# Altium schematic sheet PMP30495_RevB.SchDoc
size 431 x 279 mm; Date: Not shown in title block; ApprovedBy: Not shown in title block; CheckedBy: Not shown in title block; Author: Not shown in title block; CompanyName: Not shown in title block; Engineer: Not shown in title block; Organization: Not shown in title block; Address1: Not shown in title block; Address2: Not shown in title block; Address3: Not shown in title block; Address4: Not shown in title block; DocumentNumber: 1; Revision: Use project parameter SCH_Rev; SheetNumber: 2; SheetTotal: 3; PageSetup: Record=PageOptions¦CenterHorizontal=True¦CenterVertical=True¦PrintScale=1.00¦XCorrection=1.00¦YCorrection=1.00¦PrintKind=0¦BorderSize=5000000¦LeftOffset=0¦BottomOffset=0¦Orientation=2¦PaperLength=1000¦PaperWidth=1000¦Scale=100¦PaperSource=15¦PrintQuality=600¦MediaType=1¦DitherType=10¦PaperKind=Letter¦PrintScaleMode=1
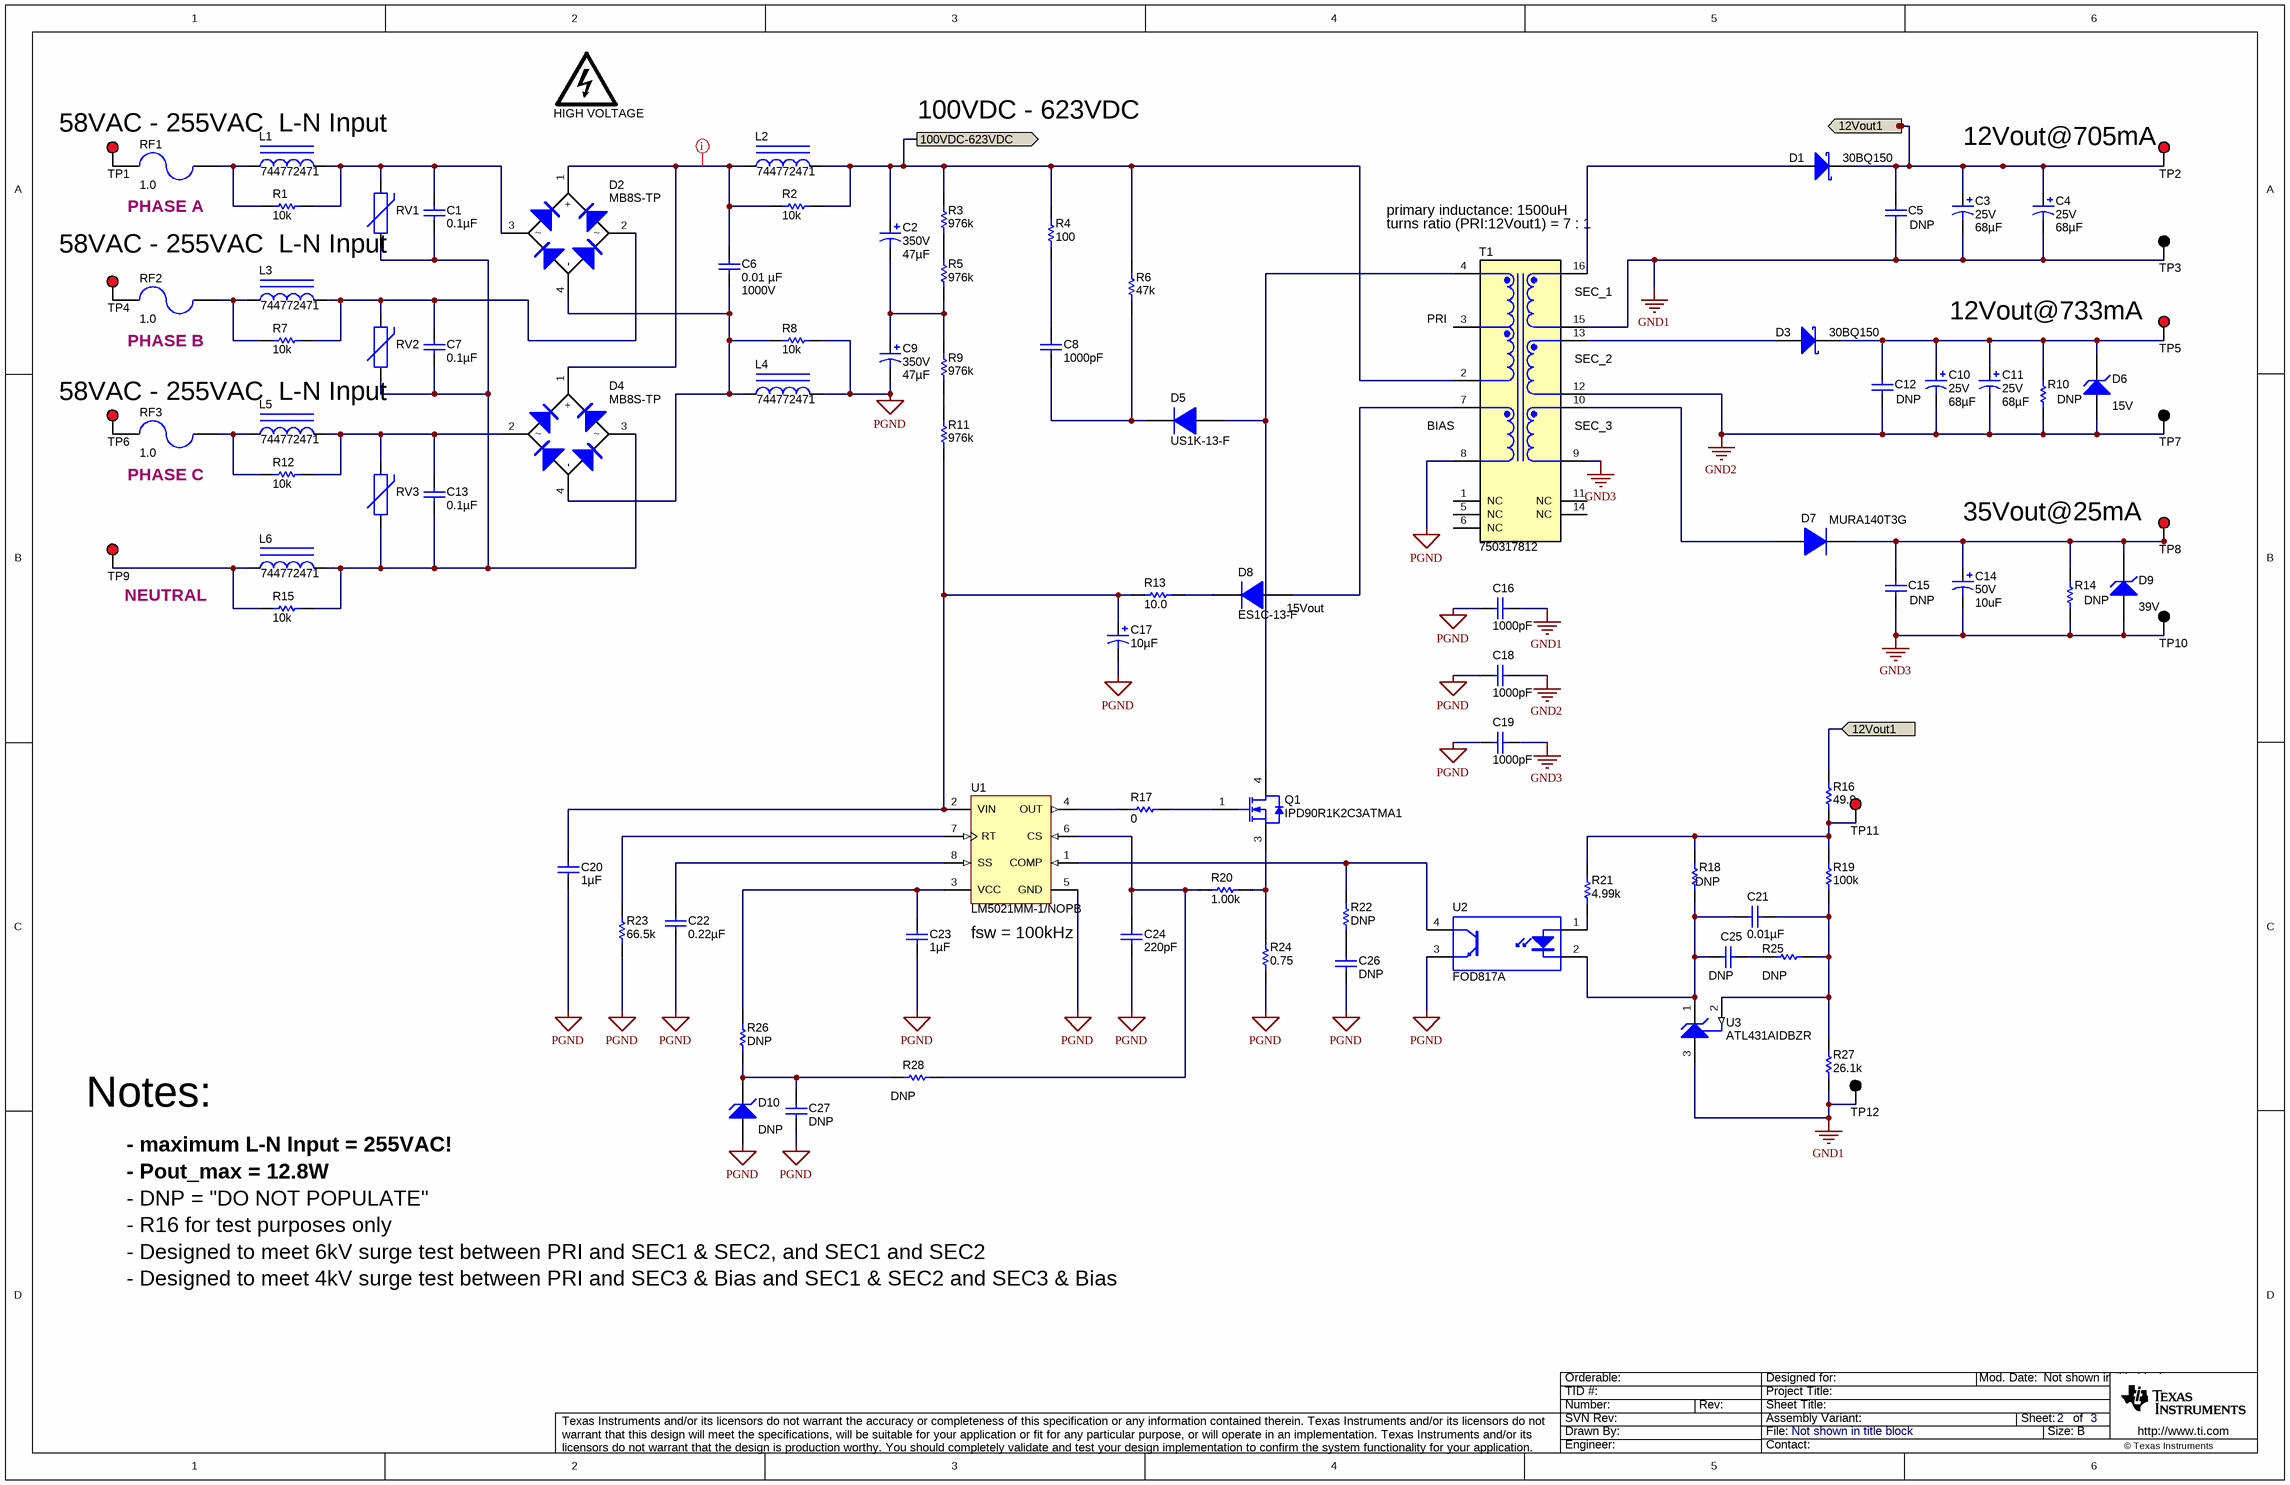
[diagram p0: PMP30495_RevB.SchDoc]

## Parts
C1  ValueDisplayed: 0.1µF  [B32921_1300x1200x600]  (hidden comment: B32921C3104M)
C2  VDC_V: 350V  ValueDisplayed: 47µF  [VR_1600x2500]  (hidden comment: UVK2V470MHD)
C3  VDC_V: 25V  ValueDisplayed: 68µF  [Nichicon_800x1000]  (hidden comment: UWG1E680MNL1GS)
C4  VDC_V: 25V  ValueDisplayed: 68µF  [Nichicon_800x1000]  (hidden comment: UWG1E680MNL1GS)
C5  value DNP  [1206]  (hidden comment: Used in BOM report)
C6  ValueDisplayed: 0.01 µF  Value2: 1000V  [B32652A_500x1050x1800]  (hidden comment: B32652A0103K)
C7  ValueDisplayed: 0.1µF  [B32921_1300x1200x600]  (hidden comment: B32921C3104M)
C8  ValueDisplayed: 1000pF  [1206]  (hidden comment: GRM31BR73A102KW01L)
C9  VDC_V: 350V  ValueDisplayed: 47µF  [VR_1600x2500]  (hidden comment: UVK2V470MHD)
C10  VDC_V: 25V  ValueDisplayed: 68µF  [Nichicon_800x1000]  (hidden comment: UWG1E680MNL1GS)
C11  VDC_V: 25V  ValueDisplayed: 68µF  [Nichicon_800x1000]  (hidden comment: UWG1E680MNL1GS)
C12  value DNP  [1206]  (hidden comment: Used in BOM report)
C13  ValueDisplayed: 0.1µF  [B32921_1300x1200x600]  (hidden comment: B32921C3104M)
C14  VDC_V: 50V  ValueDisplayed: 10uF  [SM_RADIAL_6.3AMM]  (hidden comment: UUD1H100MCL1GS)
C15  value DNP  [1206]  (hidden comment: Used in BOM report)
C16  ValueDisplayed: 1000pF  [CAPRD750W60D750H1050]  (hidden comment: VY2102M29Y5UG63V7)
C17  ValueDisplayed: 10µF  [PW_500x700]  (hidden comment: UPW1V100MDD6)
C18  ValueDisplayed: 1000pF  [CAPRD750W60D750H1050]  (hidden comment: VY2102M29Y5UG63V7)
C19  ValueDisplayed: 1000pF  [CAPRD750W60D750H1050]  (hidden comment: VY2102M29Y5UG63V7)
C20  ValueDisplayed: 1µF  [0805_HV]  (hidden comment: 08055C105KAT2A)
C21  ValueDisplayed: 0.01µF  [0603]  (hidden comment: C0603C103J5RACTU)
C22  ValueDisplayed: 0.22µF  [0603]  (hidden comment: C0603C224J3RAC7867)
C23  ValueDisplayed: 1µF  [0805_HV]  (hidden comment: 08055C105KAT2A)
C24  ValueDisplayed: 220pF  [0603]  (hidden comment: C0603C221K5RACTU)
C25  value DNP  [0603_HV]  (hidden comment: Used in BOM report)
C26  value DNP  [0603_HV]  (hidden comment: Used in BOM report)
C27  value DNP  [0805]  (hidden comment: Used in BOM report)
D1  30BQ150  [SMC]
D2  MB8S-TP  [MBS-1]
D3  30BQ150  [SMC]
D4  MB8S-TP  [MBS-1]
D5  US1K-13-F  [SMA]
D6  value 15V  [SOD-123]  (hidden comment: MMSZ5245B-7-F)
D7  MURA140T3G  [SMA]
D8  ES1C-13-F  [SMA]
D9  value 39V  [SMA]  (hidden comment: 3SMAJ5939B-TP)
D10  value DNP  [SOD-123]  (hidden comment: Used in BOM report)
HIGH_VOLTAGE  DANGER HIGH VOLTAGE  [IEC_HighVoltage_Small]  (value not drawn)  (no BOM)
L1  744772471  [WE_TI_8095_Unshielded]
L2  744772471  [WE_TI_8095_Unshielded]
L3  744772471  [WE_TI_8095_Unshielded]
L4  744772471  [WE_TI_8095_Unshielded]
L5  744772471  [WE_TI_8095_Unshielded]
L6  744772471  [WE_TI_8095_Unshielded]
Q1  IPD90R1K2C3ATMA1  [DPAK]
R1  value 10k  [1206L]  (hidden comment: CRCW120610K0JNEA)
R2  value 10k  [1206L]  (hidden comment: CRCW120610K0JNEA)
R3  ValueDisplayed: 976k  [1206]  (hidden comment: CRCW1206976KFKEA)
R4  ValueDisplayed: 100  [2010]  (hidden comment: CRCW2010100RFKEF)
R5  ValueDisplayed: 976k  [1206]  (hidden comment: CRCW1206976KFKEA)
R6  ValueDisplayed: 47k  [2512]  (hidden comment: CRCW251247K0JNEG)
R7  value 10k  [1206L]  (hidden comment: CRCW120610K0JNEA)
R8  value 10k  [1206L]  (hidden comment: CRCW120610K0JNEA)
R9  ValueDisplayed: 976k  [1206]  (hidden comment: CRCW1206976KFKEA)
R10  value DNP  [0805]  (hidden comment: Used in BOM report)
R11  ValueDisplayed: 976k  [1206]  (hidden comment: CRCW1206976KFKEA)
R12  value 10k  [1206L]  (hidden comment: CRCW120610K0JNEA)
R13  ValueDisplayed: 10.0  [0805_HV]  (hidden comment: CRCW080510R0FKEA)
R14  value DNP  [0805]  (hidden comment: Used in BOM report)
R15  value 10k  [1206L]  (hidden comment: CRCW120610K0JNEA)
R16  ValueDisplayed: 49.9  [0603]  (hidden comment: CRCW060349R9FKEA)
R17  ValueDisplayed: 0  [0805_HV]  (hidden comment: CRCW08050000Z0EA)
R18  value DNP  [0603]  (hidden comment: Used in BOM report)
R19  ValueDisplayed: 100k  [0603]  (hidden comment: CRCW0603100KFKEA)
R20  ValueDisplayed: 1.00k  [0603]  (hidden comment: CRCW06031K00FKEA)
R21  ValueDisplayed: 4.99k  [0603]  (hidden comment: CRCW06034K99FKEA)
R22  value DNP  [0603_HV]  (hidden comment: Used in BOM report)
R23  ValueDisplayed: 66.5k  [0603]  (hidden comment: CRCW060366K5FKEA)
R24  ValueDisplayed: 0.75  [1206]  (hidden comment: ERJ-8RQFR75)
R25  value DNP  [0603_HV]  (hidden comment: Used in BOM report)
R26  value DNP  [0603]  (hidden comment: Used in BOM report)
R27  ValueDisplayed: 26.1k  [0603]  (hidden comment: CRCW060326K1FKEA)
R28  value DNP  [0603]  (hidden comment: Used in BOM report)
RF1  ValueDisplayed: 1.0  [SPP_1020x380]  (hidden comment: SPP1UL1R00JLF)
RF2  ValueDisplayed: 1.0  [SPP_1020x380]  (hidden comment: SPP1UL1R00JLF)
RF3  ValueDisplayed: 1.0  [SPP_1020x380]  (hidden comment: SPP1UL1R00JLF)
RV1  B72210S2301K101  [EPCOS_B72210S2301K101]  (value not drawn)
RV2  B72210S2301K101  [EPCOS_B72210S2301K101]  (value not drawn)
RV3  B72210S2301K101  [EPCOS_B72210S2301K101]  (value not drawn)
T1  750317812  [Wurth_750317812]
TP1  5000  [Keystone5000]  (value not drawn)
TP2  5000  [Keystone5000]  (value not drawn)
TP3  5001  [Keystone5001]  (value not drawn)
TP4  5000  [Keystone5000]  (value not drawn)
TP5  5000  [Keystone5000]  (value not drawn)
TP6  5000  [Keystone5000]  (value not drawn)
TP7  5001  [Keystone5001]  (value not drawn)
TP8  5000  [Keystone5000]  (value not drawn)
TP9  5000  [Keystone5000]  (value not drawn)
TP10  5001  [Keystone5001]  (value not drawn)
TP11  5000  [Keystone5000]  (value not drawn)
TP12  5001  [Keystone5001]  (value not drawn)
U1  LM5021MM-1/NOPB  [MUA08A_N]
U2  FOD817A  [DIP-4]
U3  ATL431AIDBZR  [DBZ0003A_N]

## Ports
12Vout1 (in), 100VDC-623VDC (out)

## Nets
GND1: C3.2(-) C4.2(-) C5.2 C16.1 R27.1 T1.15 TP3.1 TP12.1 U3.3(ANODE)
GND2: C10.2(-) C11.2(-) C12.2 C18.1 D6.2(A) R10.1 T1.12 TP7.1
GND3: C14.2(-) C15.2 C19.1 D9.2(A) R14.1 T1.9 TP10.1
PGND: C9.2(-) C16.2 C17.2(-) C18.2 C19.2 C20.2 C22.2 C23.2 C24.2 C26.2 C27.2 D10.2(A) L4.2 R8.2 R23.1 R24.1 T1.8 U1.5(GND) U2.3(E)
12Vout1: C3.1(+) C4.1(+) C5.1 D1.1(K) R16.2 TP2.1 ; port 12Vout1
100VDC-623VDC: C2.1(+) L2.2 R2.2 R3.2 R4.2 R6.2 T1.2 ; port 100VDC-623VDC
NetC1_1: C1.1 D2.3 L1.2 R1.2 RV1.2
NetC1_2: C1.2 C7.2 C13.2 D4.3 L6.2 R15.2 RV1.1 RV2.1 RV3.1
NetC2_2: C2.2(-) C9.1(+) R5.1 R9.2
NetC6_1: C6.1 D2.1(+) D4.1(+) L2.1 R2.1
NetC6_2: C6.2 D2.4(-) D4.4(-) L4.1 R8.1
NetC7_1: C7.1 D2.2 L3.2 R7.2 RV2.2
NetC8_1: C8.1 R4.1
NetC8_2: C8.2 D5.1(K) R6.1
NetC10_1: C10.1(+) C11.1(+) C12.1 D3.1(K) D6.1(K) R10.2 TP5.1
NetC13_1: C13.1 D4.2 L5.2 R12.2 RV3.2
NetC14_1: C14.1(+) C15.1 D7.1(K) D9.1(K) R14.2 TP8.1
NetC17_1: C17.1(+) C20.1 R11.1 R13.1 U1.2(VIN)
NetC21_1: C21.1 R19.1 R25.1 R27.2 U3.2(REF)
NetC21_2: C21.2 C25.1 R18.1 U2.2(K) U3.1(CATHODE)
NetC22_1: C22.1 U1.8(SS)
NetC23_1: C23.1 R26.2 U1.3(VCC)
NetC24_1: C24.1 R20.1 R28.2 U1.6(CS)
NetC25_2: C25.2 R25.2
NetC26_1: C26.1 R22.1
NetC27_1: C27.1 D10.1(K) R26.1 R28.1
NetD1_2: D1.2(A) T1.16
NetD3_2: D3.2(A) T1.13
NetD5_2: D5.2(A) Q1.4(D) T1.4
NetD7_2: D7.2(A) T1.10
NetD8_1: D8.1(K) R13.2
NetD8_2: D8.2(A) T1.7
NetL1_1: L1.1 R1.1 RF1.1
NetL3_1: L3.1 R7.1 RF2.1
NetL5_1: L5.1 R12.1 RF3.1
NetL6_1: L6.1 R15.1 TP9.1
NetQ1_1: Q1.1(G) R17.2
NetQ1_3: Q1.3(S) R20.2 R24.2
NetR3_1: R3.1 R5.2
NetR9_1: R9.1 R11.2
NetR16_1: R16.1 R18.2 R19.2 R21.2 TP11.1
NetR17_1: R17.1 U1.4(OUT)
NetR21_1: R21.1 U2.1(A)
NetR22_2: R22.2 U1.1(COMP) U2.4(C)
NetR23_2: R23.2 U1.7(RT)
NetRF1_2: RF1.2 TP1.1
NetRF2_2: RF2.2 TP4.1
NetRF3_2: RF3.2 TP6.1

Not connected (* = marked no-connect by the designer): T1 1(NC) 3 5(NC) 6(NC) 11(NC) 14(NC)

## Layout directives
rule Clearance Constraint [Clearance = 25mil]: NetC6_1

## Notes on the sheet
- (near TP1) 58VAC - 255VAC  L-N Input
- 100VDC - 623VDC
- 12Vout@705mA
- (near RF1) PHASE A
- primary inductance: 1500uH
- (near T1) turns ratio (PRI:12Vout1) = 7 : 1
- (near RV1) 58VAC - 255VAC  L-N Input
- (near T1) SEC_1
- (near RF2) PHASE B
- (near T1) PRI
- (near T1) SEC_2
- 12Vout@733mA
- 58VAC - 255VAC  L-N Input
- (near T1) BIAS
- (near T1) SEC_3
- (near RF3) PHASE C
- 35Vout@25mA
- (near TP9) NEUTRAL
- (near D8) 15Vout
- fsw = 100kHz
- Notes:
- - maximum L-N Input = 255VAC!
- - DNP = "DO NOT POPULATE"
- - R16 for test purposes only
- - Pout_max = 12.8W
- - Designed to meet 6kV surge test between PRI and SEC1 & SEC2, and SEC1 and SEC2
- - Designed to meet 4kV surge test between PRI and SEC3 & Bias and SEC1 & SEC2 and SEC3 & Bias

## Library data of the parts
C1 C7 C13 = B32921C3104M: CAP, Film, 0.1uF, 305V, +/-20%, TH; Manufacturer: EPCOS Inc; Polarized: N; CompType: Capacitor; U/M: EA; Cap_F: 0.0000001; Tolerance_%: 20; Value1: Unknown; VDC_V: 305; TaMin_C: -40; TaMax_C: 110; Cap_Case: 13x12x6mm
C2 C9 = CMP-0082581-1: CAP, AL, 47 µF, 350 V, +/- 20%, TH; Manufacturer: Nichicon; IRMS_A: 300mA; SizeAreaWB_mm2: 324; SizeArea_mm2: 256; AEC Qualified: N; AEC Category: Q200; Value: 47uF; TaMax_C: 85°C; SizeZ_mm: 27; Polarized: Y; TaMin_C: -40°C; SizeY_mm: 16; U/M: EA; CompType: Capacitor; Cap_Case: 16x25mm
C3 C4 C10 C11 = CMP-0082582-1: CAP, AL, 68 µF, 25 V, +/- 20%, SMD; Manufacturer: Nichicon; IRMS_A: 450mA; SizeAreaWB_mm2: 106.09; SizeArea_mm2: 68.89; AEC Qualified: N; AEC Category: Q200; Value: 68uF; TaMax_C: 105°C; SizeZ_mm: 10.8; Polarized: Y; TaMin_C: -55°C; SizeY_mm: 8.3; U/M: EA; CompType: Capacitor; Cap_Case: 8x10mm
C5 C12 C15 C25-C27 = Capacitor: CAP, CERM, xxxF, xxV, [TempCo], xx%, [PackageReference]; Polarized: N; U/M: EA
C6 = B32652A0103K: CAP, Film, 0.01uF, 1000V, +/-10%, TH; Manufacturer: EPCOS Inc; Polarized: N; CompType: Capacitor; U/M: EA; Cap_F: 0.00000001; Tolerance_%: 10; Value1: Unknown; VDC_V: 1000; TaMin_C: -55; TaMax_C: 110; Cap_Case: 5x10.5x18
C8 = GRM31BR73A102KW01L: CAP, CERM, 1000 pF, 1000 V,+/- 10%, X7R, 1206; Manufacturer: MuRata; Polarized: N; CompType: Capacitor; Value: 1000pF; U/M: EA; Cap_F: 0.000000001; Tolerance_%: 10; VDC_V: 1000; Value2: 1000V; TaMin_C: -55; TaMax_C: 125; SizeArea_mm2: 5.12; SizeAreaWB_mm2: 10.92; SizeX_mm: 3.2; SizeY_mm: 1.6; SizeZ_mm: 1.35; AEC Category: Q200; Green_Lifecycle: Not Set; Green_REACh: Incomplete
C14 = CMP-0011413-2: CAP, AL, 10 uF, 50 V, +/- 20%, 0.88 ohm, SMD; Manufacturer: Nichicon; TaMin_C: -55°C; ESR_ohm: 8.8d; Polarized: Y; SizeAreaWB_mm2: 79.98; U/M: EA; Value: 10uF; TaMax_C: 105°C; SizeZ_mm: 6; SizeX_mm: 7.3; SizeY_mm: 6.6; Cap_Case: 6.3x5.8; SizeArea_mm2: 48.18; CompType: Capacitor; Cap_F: 10µF; IRMS_A: 1.65dA; AEC Category: Q200
C16 C18 C19 = VY2102M29Y5UG63V7: CAP, CERM, 1000pF, 300V, +/-20%, Y5U, Radial Disc 7.5mm, ls=7.5; Manufacturer: Vishay-Bccomponents; Polarized: N; CompType: Capacitor; U/M: EA; Cap_F: 0.000000001; Tolerance_%: 20; Value1: Unknown; VDC_V: 300; TaMin_C: -40; TaMax_C: 125
C17 = UPW1V100MDD6: CAP, AL, 10 µF, 35 V, +/- 20%, 0.95 ohm, TH; Manufacturer: Nichicon; Polarized: Y; CompType: Capacitor; Value: 10uF; U/M: EA; Cap_F: 0.00001; Tolerance_%: 20; VDC_V: 35; Value2: 35V; ESR_ohm: 0.95; IRMS_A: 0.12; TaMin_C: -55; TaMax_C: 105; Cap_Case: 5x7; SizeAreaWB_mm2: 49; SizeArea_mm2: 25; SizeX_mm: 5; SizeZ_mm: 8; AEC Category: Q200; Green_Lifecycle: Active; Green_REACh: Passed
C20 = 08055C105KAT2A: CAP, CERM, 1 µF, 50 V,+/- 10%, X7R, 0805; Manufacturer: AVX; Polarized: N; CompType: Capacitor; Value: 1uF; U/M: EA; Cap_F: 0.000001; Tolerance_%: 10; VDC_V: 50; Value2: 50V; TaMin_C: -55; TaMax_C: 125; Cap_Case: 0805; SizeArea_mm2: 2.5; SizeAreaWB_mm2: 6.75; SizeX_mm: 2; SizeY_mm: 1.25; SizeZ_mm: 1.45; AEC Category: Q200; Green_Lifecycle: Active; Green_REACh: Passed
C21 = C0603C103J5RACTU: CAP, CERM, 0.01 µF, 50 V,+/- 5%, X7R, 0603; Manufacturer: Kemet; Polarized: N; CompType: Capacitor; Value: 0.01uF; U/M: EA; Cap_F: 0.00000001; Tolerance_%: 5; VDC_V: 50; Value2: 50V; TaMin_C: -55; TaMax_C: 125; SizeArea_mm2: 1.28; SizeAreaWB_mm2: 4.68; SizeX_mm: 1.6; SizeY_mm: 0.8; SizeZ_mm: 1; AEC Category: Q200; Green_Lifecycle: Active; Green_REACh: Passed
C22 = C0603C224J3RAC7867: CAP, CERM, 0.22 µF, 25 V,+/- 5%, X7R, 0603; Manufacturer: Kemet; Polarized: N; CompType: Capacitor; Value: 0.22uF; U/M: EA; Cap_F: 0.00000022; Tolerance_%: 5; VDC_V: 25; Value2: 25V; TaMin_C: -55; TaMax_C: 125; SizeArea_mm2: 1.28; SizeAreaWB_mm2: 4.68; SizeX_mm: 1.6; SizeY_mm: 0.8; SizeZ_mm: 1; AEC Category: Q200; Green_Lifecycle: Active; Green_REACh: Passed
C23 = 08055C105KAT2A: CAP, CERM, 1 µF, 50 V, +/- 10%, X7R, 0805; Manufacturer: AVX; Polarized: N; CompType: Capacitor; Value: 1uF; U/M: EA; Cap_F: 0.000001; Tolerance_%: 10; Value1: Unknown; VDC_V: 50; Value2: 50V; TaMin_C: -55; TaMax_C: 125; Cap_Case: 0805
C24 = C0603C221K5RACTU: CAP, CERM, 220 pF, 50 V,+/- 10%, X7R, 0603; Manufacturer: Kemet; Polarized: N; CompType: Capacitor; Value: 220pF; U/M: EA; Cap_F: 0.00000000022; Tolerance_%: 10; VDC_V: 50; Value2: 50V; TaMin_C: -55; TaMax_C: 125; SizeArea_mm2: 1.28; SizeAreaWB_mm2: 4.68; SizeX_mm: 1.6; SizeY_mm: 0.8; SizeZ_mm: 1; AEC Category: Q200; Green_Lifecycle: Active; Green_REACh: Passed
D1 D3 = Diode_Schottky: Diode, Schottky, 150V, xxA, [PackageReference]; Manufacturer: Used in BOM report; U/M: EA
D2 D4 = MB8S-TP: Diode, Switching-Bridge, 800V, 0.5A, 4-Pin TO269AA, Body 4.95 x 4.2 mm, Pitch 2.555 mm; Manufacturer: Micro Commercial Components; U/M: EA; Vf_V: 1; Value2: 1V; Io_A: 0.5; Vr_V: 800; TJmax_C: 150
D5 = US1K-13-F: Diode, Fast Rectifier, 800 V, 1 A, SMA; Manufacturer: Diodes Inc.; U/M: EA; Vf_V: 1.7; Value: 800V; Value1: 1A; Value2: 1.7V; Io_A: 1; Vr_V: 800; TJmax_C: 150; SizeAreaWB_mm2: 37.3428; SizeArea_mm2: 16.3228; SizeX_mm: 5.59; SizeY_mm: 2.92; SizeZ_mm: 2.87; AEC Category: Q101; Green_Lifecycle: Not Set; Green_REACh: Incomplete
D6 = MMSZ5245B-7-F: Diode, Zener, 15 V, 500 mW, SOD-123; Manufacturer: Diodes Inc.; SymbolCreator: a0412235; U/M: EA; Power_W: 0.5; Vz_V: 15; Value1: 0.5W; RJA_CperW: 350; SizeAreaWB_mm2: 13.095; SizeArea_mm2: 6.545; SizeX_mm: 3.85; SizeY_mm: 1.7; SizeZ_mm: 1.35; AEC Category: Q101; Green_Lifecycle: Active; Green_REACh: Passed
D7 = CMP-0029038-1: Diode, Ultrafast, 400 V, 1 A, SMA; Manufacturer: ON Semiconductor; Io_A: 1A; Green_Lifecycle: Active; SizeAreaWB_mm2: 37.3428; Vr_V: 400V; Green_REACh: Passed; TJmax_C: 175°C; U/M: EA; Value: 400V; SizeZ_mm: 2.87; SizeX_mm: 5.59; SizeY_mm: 2.92; Vf_V: 87.5mV; Value2: 0.0875V; SizeArea_mm2: 16.3228; AEC Category: Q101
D8 = CMP-0029023-1: Diode, Superfast Rectifier, 150 V, 1 A, SMA; Manufacturer: Diodes Inc.; Io_A: 1A; Green_Lifecycle: Not Set; SizeAreaWB_mm2: 37.3428; Vr_V: 150V; Green_REACh: Incomplete; TJmax_C: 150°C; U/M: EA; Value: 150V; SizeZ_mm: 2.87; SizeX_mm: 5.59; SizeY_mm: 2.92; Vf_V: 9.2dV; Value2: 0.92V; SizeArea_mm2: 16.3228; AEC Category: Q101; RJC_CperW: 25
D9 = 3SMAJ5939B-TP: Diode, Zener, 39 V, 3 W, SMA; Manufacturer: Micro Commercial Components; SymbolCreator: a0412235; U/M: EA; Power_W: 3; Vz_V: 39; Value1: 3W; RJA_CperW: 226; SizeAreaWB_mm2: 37.3428; SizeArea_mm2: 16.3228; SizeX_mm: 5.59; SizeY_mm: 2.92; SizeZ_mm: 2.87; AEC Category: Q101
D10 = Zener: Diode, Zener, xxV, xxxmW, [PackageReference]; SymbolCreator: a0412235; U/M: EA
HIGH_VOLTAGE = IEC_HighVoltage: IEC 61010-1 High Voltage Warning; SymbolCreator: a0412235
L1-L6 = 744772221: Inductor, Wirewound, Ferrite, 470 µH; Manufacturer: Wurth Elektronik; Value: 470uH; ValueDisplayed: 470µH; Ind_H: 220.0E-6; Imax_A: 0.64; Irms: 0.64A @ 40C rise; Isat: 1.2A @ 10% inductance drop; DCR_ohm: 0.351; SizeAreaWB_mm2: 96.04; SizeArea_mm2: 60.84; SizeX_mm: 7.8; SizeZ_mm: 10; AEC Category: Q200; Green_Lifecycle: Active; Green_REACh: Passed
Q1 = CMP-0074794-1: MOSFET, N-CH, 900 V, 5.1 A, DPAK; Alternate Manufacturer: None; Manufacturer: Infineon Technologies; QgTyp_nC: 28.0; SizeAreaWB_mm2: 101.7114; Vgs_V: 20V; Value1: ? ohm; VdsMax_V: 900V; U/M: EA; Value: 900V; IdsMax_A: 5.1A; SizeZ_mm: 2.29; SizeX_mm: 9.91; SizeY_mm: 6.54; Value2: 28 nC; SizeArea_mm2: 64.8114; ChType: N; AEC Category: Q101
R1 R2 R7 R8 R12 R15 = CRCW120610K0JNEA: RES, 10k ohm, 5%, 0.25W, 1206; Manufacturer: Vishay-Dale; CompType: Resistor; Res_ohm: 10000; Value_Code: 10k0; Tolerance_%: 5; Power_W: 0.25; VDC_V: 200; TempCo: 200 ppm/C; EIA_Code: E24; U/M: EA
R3 R5 R9 R11 = CRCW1206976KFKEA: RES, 976 k, 1%, 0.25 W, 1206; Manufacturer: Vishay-Dale; CompType: Resistor; Value: 976k; Res_ohm: 976000; Tolerance_%: 1; Power_W: 0.25; Value2: 0.25W; VDC_V: 200; TempCo: 100 ppm/C; SizeArea_mm2: 5.12; SizeX_mm: 3.2; SizeY_mm: 1.6; SizeZ_mm: 1.35; EIA_Code: E96; U/M: EA; AEC Category: Q200
R4 = CRCW2010100RFKEF: RES, 100, 1%, 0.75 W, AEC-Q200 Grade 0, 2010; Manufacturer: Vishay-Dale; CompType: Resistor; Value: 100; Value_Code: 100R; Tolerance_%: 1; Power_W: 0.75; Value2: 0.75W; VDC_V: 400; TempCo: 100 ppm/C; SizeArea_mm2: 12.5; SizeX_mm: 5; SizeY_mm: 2.5; SizeZ_mm: 1.66; EIA_Code: E96; U/M: EA; AEC Category: Q200; AEC Qualified: Y; AEC Grade: 0
R6 = CRCW251247K0JNEG: RES, 47 k, 5%, 1 W, AEC-Q200 Grade 0, 2512; Manufacturer: Vishay-Dale; CompType: Resistor; Value: 47k; Res_ohm: 47000; Value_Code: 47k0; Tolerance_%: 5; Power_W: 1; Value2: 1W; VDC_V: 500; TempCo: 200 ppm/C; SizeArea_mm2: 20.16; SizeX_mm: 6.3; SizeY_mm: 3.2; SizeZ_mm: 0.71; EIA_Code: E24; U/M: EA; AEC Category: Q200; AEC Qualified: Y; AEC Grade: 0
R10 R14 R18 R22 R25 R26 R28 = Resistor: RES, xxx ohm, x%, xW, [PackageReference]; U/M: EA
R13 = CRCW080510R0FKEA: RES, 10.0, 1%, 0.125 W, 0805; Manufacturer: Vishay-Dale; CompType: Resistor; Value: 10.0; Res_ohm: 10; Value_Code: 10R0; Tolerance_%: 1; Power_W: 0.125; Value2: 0.125W; VDC_V: 150; TempCo: 100 ppm/C; EIA_Code: E96; U/M: EA
R16 = CRCW060349R9FKEA: RES, 49.9, 1%, 0.1 W, 0603; Manufacturer: Vishay-Dale; CompType: Resistor; Value: 49.9; Value_Code: 49R9; Tolerance_%: 1; Power_W: 0.1; Value2: 0.1W; VDC_V: 75; TempCo: 100 ppm/C; EIA_Code: E96; U/M: EA
R17 = CRCW08050000Z0EA: RES, 0, 5%, 0.125 W, 0805; Manufacturer: Vishay-Dale; CompType: Resistor; Value: 0; Value_Code: 0000; Tolerance_%: 5; Power_W: 0.125; Value2: 0.125W; VDC_V: 150; TempCo: 200 ppm/C; EIA_Code: E24; U/M: EA
R19 = CRCW0603100KFKEA: RES, 100 k, 1%, 0.1 W, 0603; Manufacturer: Vishay-Dale; CompType: Resistor; Value: 100k; Res_ohm: 100000; Tolerance_%: 1; Power_W: 0.1; Value2: 0.1W; VDC_V: 75; TempCo: 100 ppm/C; SizeArea_mm2: 1.28; SizeX_mm: 1.6; SizeY_mm: 0.8; EIA_Code: E96; U/M: EA; AEC Category: Q200; Green_Lifecycle: Active; Green_REACh: Passed
R20 = CRCW06031K00FKEA: RES, 1.00 k, 1%, 0.1 W, 0603; Manufacturer: Vishay-Dale; CompType: Resistor; Value: 1.00k; Res_ohm: 1000; Value_Code: 1k00; Tolerance_%: 1; Power_W: 0.1; Value2: 0.1W; VDC_V: 75; TempCo: 100 ppm/C; SizeArea_mm2: 1.28; SizeX_mm: 1.6; SizeY_mm: 0.8; EIA_Code: E96; U/M: EA; AEC Category: Q200; Green_Lifecycle: Active; Green_REACh: Passed
R21 = CRCW06034K99FKEA: RES, 4.99 k, 1%, 0.1 W, 0603; Manufacturer: Vishay-Dale; CompType: Resistor; Value: 4.99k; Res_ohm: 4990; Value_Code: 4k99; Tolerance_%: 1; Power_W: 0.1; Value2: 0.1W; VDC_V: 75; TempCo: 100 ppm/C; SizeArea_mm2: 1.28; SizeX_mm: 1.6; SizeY_mm: 0.8; EIA_Code: E96; U/M: EA; AEC Category: Q200; Green_Lifecycle: Active; Green_REACh: Passed
R23 = CRCW060366K5FKEA: RES, 66.5 k, 1%, 0.1 W, 0603; Manufacturer: Vishay-Dale; CompType: Resistor; Value: 66.5k; Res_ohm: 66500; Value_Code: 66k5; Tolerance_%: 1; Power_W: 0.1; Value2: 0.1W; VDC_V: 75; TempCo: 100 ppm/C; SizeArea_mm2: 1.28; SizeX_mm: 1.6; SizeY_mm: 0.8; EIA_Code: E96; U/M: EA; AEC Category: Q200; Green_Lifecycle: Active; Green_REACh: Passed
R24 = ERJ-8RQFR68V: RES, 0.75, 1%, 0.25 W, 1206; Manufacturer: Panasonic; CompType: Resistor; Value: 0.75; Value_Code: R75; Tolerance_%: 1; Power_W: 0.25; Value2: 0.25W; TempCo: 250 ppm/C; SizeArea_mm2: 5.12; SizeX_mm: 3.2; SizeY_mm: 1.6; SizeZ_mm: 1.35; EIA_Code: E96; U/M: EA; AEC Category: Q200
R27 = CRCW060326K1FKEA: RES, 26.1 k, 1%, 0.1 W, 0603; Manufacturer: Vishay-Dale; CompType: Resistor; Value: 26.1k; Res_ohm: 26100; Value_Code: 26k1; Tolerance_%: 1; Power_W: 0.1; Value2: 0.1W; VDC_V: 75; TempCo: 100 ppm/C; SizeArea_mm2: 1.28; SizeX_mm: 1.6; SizeY_mm: 0.8; EIA_Code: E96; U/M: EA; AEC Category: Q200; Green_Lifecycle: Active; Green_REACh: Passed
RF1-RF3 = SPP1UL1R00JLF: RES, 1.0, 5%, 1 W, TH; Manufacturer: TT Electronics/IRC; SymbolCreator: a0412235; CompType: Resistor; Res_ohm: 1; Value: 1.0; Value_Code: 1R00; Tolerance_%: 5; Value2: 1W; TempCo: 300 ppm/C; EIA_Code: E24; U/M: EA
RV1-RV3 = B72210S2301K101: SIOV Metal Oxide Leaded Varistor, 300VAC, 3500A, TH; Manufacturer: EPCOS Inc; SymbolCreator: a0412235
T1 = CMP-0083732-1: Transformer, 1500 uH, TH; Manufacturer: Wurth Elektronik; Rsec3_ohm: 0.5; SizeAreaWB_mm2: 2022.75; SizeArea_mm2: 1846.75; AEC Qualified: N; Ns2toNp: 0.143; Lp: 1500; AEC Category: Q200; Value: 1.5mH; SizeZ_mm: 30; SizeY_mm: 41.5; Rsec2_ohm: 0.07; SizeX_mm: 44.5; DCR_ohm: 2.2; Ns3toNp: 0.4
TP1 TP2 TP4-TP6 TP8 TP9 = 5000: Test Point, Miniature, Red, TH; Manufacturer: Keystone; CompType: Test Point Loop; ContactFinish: Silver; Green_Lifecycle: Active; Green_REACh: Passed
TP3 TP7 TP10 = 5001: Test Point, Miniature, Black, TH; Manufacturer: Keystone; CompType: Test Point Loop; ContactFinish: Silver; Green_Lifecycle: Active; Green_REACh: Passed
TP11 = 5000: Test Point, Miniature, Red, TH; Manufacturer: Keystone; CompType: Test Point Loop; U/M: EA
TP12 = 5001: Test Point, Miniature, Black, TH; Manufacturer: Keystone; CompType: Test Point Loop; U/M: EA
U1 = LM5021MM-1/NOPB: AC-DC Current Mode PWM Controller, 8-pin MSOP, Pb-Free; Manufacturer: Texas Instruments; PackageTopMarking: ZXTT*21-1; PowerWise: N; CompType: Switcher
U2 = FOD817A: Optocoupler, 5 kV, 80-160% CTR, TH; Manufacturer: Fairchild Semiconductor; CTR (Min): 80%; CTR (Max): 160%; Voltage_Isolation_Vrms: 5000V; SizeAreaWB_mm2: 71.064; SizeArea_mm2: 40.304; SizeX_mm: 8.8; SizeY_mm: 4.58; SizeZ_mm: 5
U3 = ATL431AIDBZR: 2.5V Low Iq Adjustable Precision Shunt Regulator, DBZ0003A (SOT-23-3); Manufacturer: Texas Instruments; SymbolCreator: a0412235; SizeArea_mm2: 7.5; SizeAreaWB_mm2: 14; SizeX_mm: 2.5; SizeY_mm: 3; SizeZ_mm: 1.12; CompType: IC; U/M: EA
